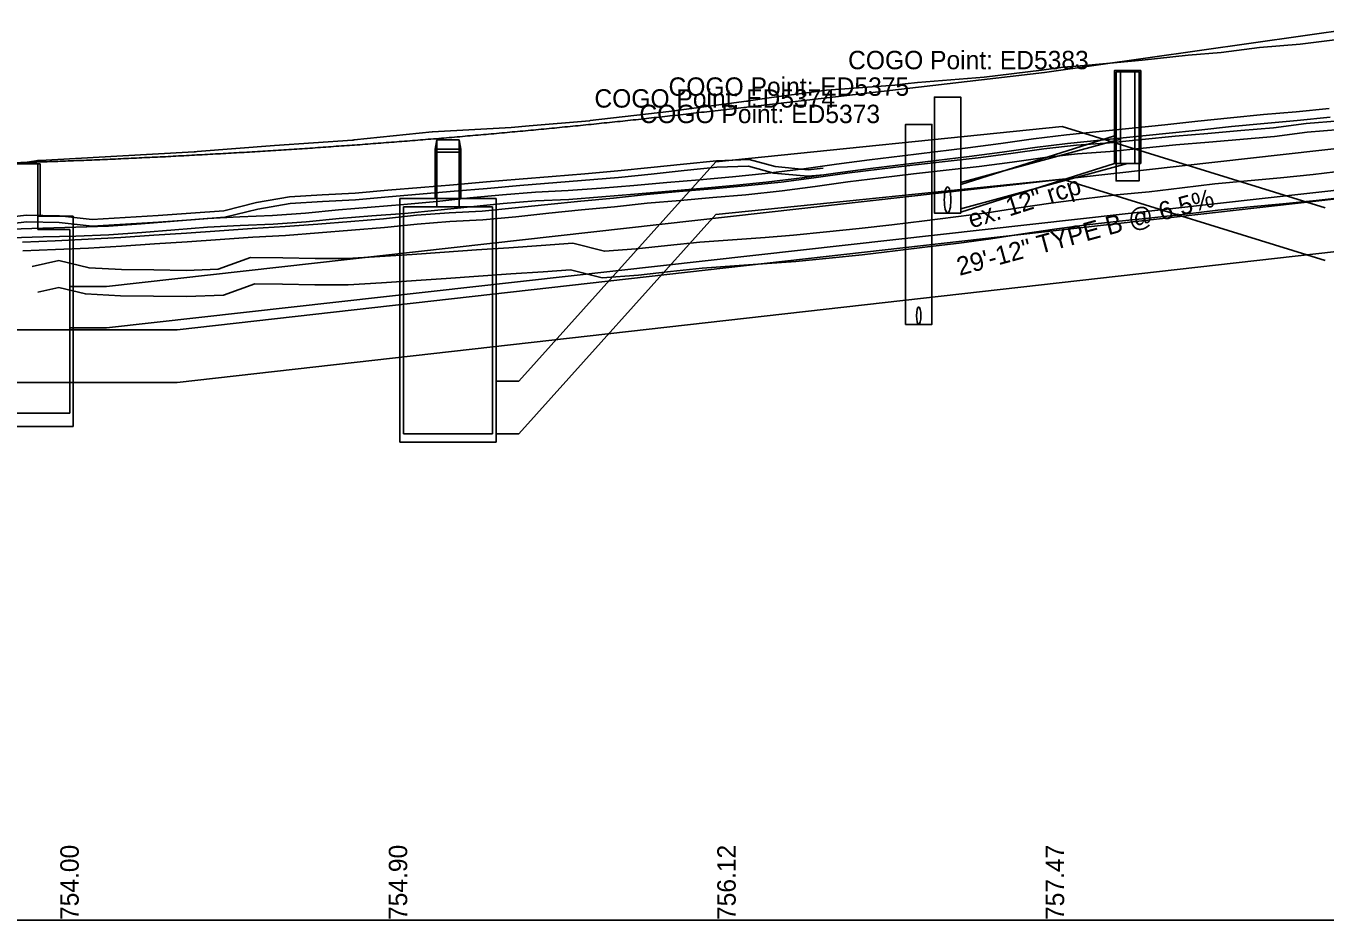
# Model space of a CAD drawing. Extents: x 1833473 to 1837132, y 704683 to 706683.
# Drawn here: x 1834152.8 to 1834350.5, y 705682.6 to 705818.8 of the extents above; entities that cross this region are included whole.
import ezdxf

# ---------------------------------------------------------------- set-up
doc = ezdxf.new("R2010")
doc.units = 0
for name, color, linetype in [('DR_P_Text', 7, 'Continuous'), ('DR_X_Storm_Sewer', 7, 'Continuous'), ('DR_X_Text', 7, 'Continuous'), ('GK_Cells', 7, 'Continuous'), ('PF_P_Grade_Line', 7, 'Continuous'), ('PF_X_Ground_Line', 7, 'Continuous'), ('PF_X_Text', 7, 'Continuous'), ('SC_Scratch1', 7, 'Continuous'), ('UT_P_Electric', 7, 'Continuous'), ('UT_P_Telecom', 7, 'Continuous'), ('UT_X_Electric', 7, 'Continuous'), ('UT_X_Gas', 7, 'Continuous'), ('UT_X_Sanitary_Line', 7, 'Continuous'), ('UT_X_Water', 7, 'Continuous')]:
    doc.layers.add(name, color=color, linetype=linetype)

msp = doc.modelspace()

# ---------------------------------------------------------------- linework, layer by layer
at = {"layer": 'DR_X_Storm_Sewer'}
for p, q in [((1834295.04, 705794.61), (1834318.44, 705802.05)), ((1834319.36, 705801.55), (1834295.04, 705794.93)), ((1834295.04, 705790.41), (1834318.44, 705797.85)), ((1834320.44, 705797.85), (1834295.04, 705790.93))]:
    msp.add_line(p, q, dxfattribs=at)
for points in [[(1834320.44, 705811.97), (1834318.44, 705811.97), (1834318.44, 705797.85), (1834322.44, 705797.85), (1834322.44, 705811.97), (1834320.44, 705811.97)], [(1834318.69, 705811.81), (1834318.69, 705795.18), (1834322.19, 705795.18), (1834322.19, 705811.81), (1834318.69, 705811.81)], [(1834319.36, 705811.81), (1834319.36, 705797.85), (1834321.52, 705797.85), (1834321.52, 705811.81)], [(1834293.04, 705807.93), (1834291.04, 705807.93), (1834291.04, 705790.29), (1834295.04, 705790.29), (1834295.04, 705807.93), (1834293.04, 705807.93)]]:
    msp.add_lwpolyline(points, dxfattribs=at)
msp.add_ellipse((1834293.04, 705792.29), major_axis=(0, 2), ratio=0.25, dxfattribs=at)
at = {"layer": 'GK_Cells'}
msp.add_line((1833710.78, 705682.65), (1834910.78, 705682.65), dxfattribs=at)
msp.add_line((1833710.78, 705682.65), (1834910.78, 705682.65), dxfattribs=at)
at = {"layer": 'PF_P_Grade_Line'}
for p, q in [((1834307.78, 705811.69), (1834357.78, 705818.77)), ((1834256.78, 705805.76), (1834307.78, 705811.69))]:
    msp.add_line(p, q, dxfattribs=at)
msp.add_spline([(1834096.78, 705797.41), (1834099.98, 705797.37), (1834103.18, 705797.35), (1834106.38, 705797.33), (1834109.58, 705797.32), (1834112.78, 705797.32), (1834115.98, 705797.33), (1834119.18, 705797.34), (1834122.38, 705797.36), (1834125.58, 705797.4), (1834128.78, 705797.44), (1834131.98, 705797.48), (1834135.18, 705797.54), (1834138.38, 705797.6), (1834141.58, 705797.68), (1834144.78, 705797.76), (1834147.98, 705797.85), (1834151.18, 705797.94), (1834154.38, 705798.05), (1834157.58, 705798.16), (1834160.78, 705798.28), (1834163.98, 705798.41), (1834167.18, 705798.55), (1834170.38, 705798.7), (1834173.58, 705798.85), (1834176.78, 705799.02), (1834179.98, 705799.19), (1834183.18, 705799.37), (1834186.38, 705799.55), (1834189.58, 705799.75), (1834192.78, 705799.95), (1834195.98, 705800.16), (1834199.18, 705800.39), (1834202.38, 705800.61), (1834205.58, 705800.85), (1834208.78, 705801.1), (1834211.98, 705801.35), (1834215.18, 705801.61), (1834218.38, 705801.88), (1834221.58, 705802.16), (1834224.78, 705802.44), (1834227.98, 705802.74), (1834231.18, 705803.04), (1834234.38, 705803.35), (1834237.58, 705803.67), (1834240.78, 705804), (1834243.98, 705804.33), (1834247.18, 705804.68), (1834250.38, 705805.03), (1834253.58, 705805.39), (1834256.78, 705805.76)], degree=3, dxfattribs=at)
at = {"layer": 'PF_X_Ground_Line'}
for points in [[(1834154.4, 705798.24), (1834154.57, 705798.27), (1834154.89, 705798.28), (1834166.57, 705798.97), (1834178.36, 705799.6), (1834178.57, 705799.62), (1834178.79, 705799.64), (1834190.57, 705800.55), (1834202.46, 705801.4), (1834202.57, 705801.4), (1834202.69, 705801.41), (1834214.57, 705802.65), (1834214.64, 705802.65), (1834226.58, 705803.3), (1834229.37, 705803.55), (1834238.54, 705804.35), (1834238.58, 705804.35), (1834238.61, 705804.36), (1834250.58, 705805.76), (1834262.44, 705807.33), (1834262.58, 705807.34), (1834262.72, 705807.36), (1834265.86, 705807.81), (1834274.59, 705809.02), (1834284.99, 705809.77), (1834286.6, 705809.97), (1834288.48, 705810.16), (1834298.62, 705810.96), (1834307.32, 705812.04), (1834310.64, 705812.51), (1834314.5, 705812.79), (1834322.65, 705813.54), (1834329.65, 705814.31), (1834334.67, 705814.74), (1834340.52, 705815.49), (1834346.68, 705816.02), (1834351.98, 705816.68)], [(1834148, 705797.28), (1834154.25, 705798.22), (1834154.4, 705798.24)]]:
    msp.add_lwpolyline(points, dxfattribs=at)
at = {"layer": 'UT_P_Electric'}
for p, q in [((1834165.01, 705779.12), (1834367.13, 705801.76)), ((1834149.99, 705797.8), (1834154.91, 705797.8)), ((1834154.57, 705787.8), (1834154.57, 705797.8)), ((1834154.91, 705789.8), (1834154.91, 705797.8)), ((1834165.01, 705772.79), (1834367.13, 705795.43)), ((1834154.57, 705789.8), (1834159.95, 705789.8)), ((1834159.95, 705789.8), (1834159.95, 705757.8)), ((1834154.57, 705787.8), (1834159.45, 705787.8)), ((1834159.45, 705787.8), (1834159.45, 705759.8)), ((1834165.01, 705779.12), (1834159.45, 705779.12)), ((1834165.01, 705772.79), (1834159.45, 705772.79)), ((1834159.45, 705759.8), (1834145.45, 705759.8)), ((1834159.95, 705757.8), (1834144.95, 705757.8))]:
    msp.add_line(p, q, dxfattribs=at)
at = {"layer": 'UT_P_Telecom'}
for p, q in [((1834175.78, 705772.5), (1834410.78, 705799.07)), ((1834175.78, 705764.5), (1834410.78, 705791.07)), ((1834142.47, 705772.5), (1834175.78, 705772.5)), ((1834142.47, 705764.5), (1834175.78, 705764.5))]:
    msp.add_line(p, q, dxfattribs=at)
at = {"layer": 'UT_X_Electric'}
for p, q in [((1834257.75, 705798.09), (1834310.49, 705803.46)), ((1834310.49, 705803.46), (1834350.49, 705791.07)), ((1834215.04, 705800.01), (1834215.3, 705801.41)), ((1834215.04, 705792.49), (1834215.04, 705800.01)), ((1834215.04, 705800.01), (1834218.93, 705800)), ((1834215.04, 705799.55), (1834218.91, 705799.55)), ((1834215.3, 705791.25), (1834215.3, 705801.41)), ((1834215.3, 705801.41), (1834218.68, 705801.41)), ((1834218.68, 705801.41), (1834218.68, 705791.25)), ((1834218.68, 705801.41), (1834218.93, 705800)), ((1834218.93, 705800), (1834218.93, 705792.49)), ((1834227.75, 705764.7), (1834257.75, 705798.09)), ((1834257.75, 705790.07), (1834310.49, 705795.45)), ((1834310.49, 705795.45), (1834350.49, 705783.06)), ((1834209.66, 705792.49), (1834224.31, 705792.49)), ((1834209.66, 705792.49), (1834209.66, 705755.4)), ((1834224.31, 705792.49), (1834224.31, 705755.4)), ((1834210.23, 705791.25), (1834223.75, 705791.25)), ((1834210.23, 705756.69), (1834210.23, 705791.25)), ((1834223.75, 705756.69), (1834223.75, 705791.25)), ((1834227.75, 705756.69), (1834257.75, 705790.07)), ((1834224.31, 705764.7), (1834227.75, 705764.7)), ((1834210.23, 705756.69), (1834223.75, 705756.69)), ((1834224.31, 705756.69), (1834227.75, 705756.69)), ((1834209.66, 705755.4), (1834224.31, 705755.4))]:
    msp.add_line(p, q, dxfattribs=at)
for points in [[(1834150.32, 705787.83), (1834155.32, 705787.98), (1834160.32, 705788.12), (1834165.32, 705788.29), (1834170.31, 705788.63), (1834175.31, 705789.06), (1834180.31, 705789.45), (1834185.3, 705789.71), (1834190.3, 705789.92), (1834195.3, 705790.29), (1834200.3, 705790.79), (1834205.29, 705791.19), (1834210.29, 705791.57), (1834215.29, 705792.05), (1834220.29, 705792.58), (1834225.29, 705793.08), (1834230.29, 705793.46), (1834235.29, 705793.7), (1834240.29, 705794.06), (1834245.29, 705794.5), (1834250.29, 705794.93), (1834255.29, 705795.36), (1834260.29, 705795.79), (1834265.29, 705796.33), (1834271.16, 705797.03), (1834276.15, 705797.73), (1834281.15, 705798.39), (1834286.15, 705799), (1834291.14, 705799.6), (1834296.14, 705800.23), (1834301.14, 705800.9), (1834306.13, 705801.61), (1834311.13, 705802.22), (1834316.13, 705802.68), (1834321.12, 705803.2), (1834326.12, 705803.73), (1834331.12, 705804.26), (1834336.11, 705804.79), (1834341.11, 705805.27), (1834346.1, 705805.71), (1834351.1, 705806.22)], [(1834150.38, 705786.49), (1834155.36, 705786.65), (1834160.36, 705786.79), (1834165.38, 705786.96), (1834170.41, 705787.3), (1834175.42, 705787.73), (1834180.39, 705788.12), (1834185.37, 705788.38), (1834190.38, 705788.59), (1834195.41, 705788.96), (1834200.41, 705789.46), (1834205.4, 705789.86), (1834210.41, 705790.24), (1834215.43, 705790.73), (1834220.43, 705791.25), (1834225.41, 705791.75), (1834230.37, 705792.13), (1834235.37, 705792.37), (1834240.4, 705792.73), (1834245.4, 705793.17), (1834255.4, 705794.03), (1834260.42, 705794.47), (1834265.44, 705795.01), (1834271.33, 705795.7), (1834276.33, 705796.41), (1834281.32, 705797.07), (1834291.3, 705798.28), (1834296.31, 705798.9), (1834301.32, 705799.58), (1834306.31, 705800.29), (1834311.27, 705800.89), (1834316.26, 705801.36), (1834321.26, 705801.87), (1834326.26, 705802.4), (1834331.26, 705802.93), (1834336.25, 705803.46), (1834341.23, 705803.94), (1834346.23, 705804.38), (1834351.25, 705804.89)], [(1834152.2, 705785.86), (1834157.2, 705786.08), (1834162.2, 705786.29), (1834167.2, 705786.55), (1834172.2, 705786.93), (1834177.2, 705787.24), (1834182.2, 705787.59), (1834187.19, 705787.95), (1834192.19, 705788.22), (1834197.19, 705788.6), (1834202.19, 705788.99), (1834207.19, 705789.43), (1834212.19, 705789.94), (1834217.19, 705790.32), (1834222.19, 705790.58), (1834227.19, 705791.06), (1834232.19, 705791.61), (1834237.19, 705792.11), (1834242.19, 705792.56), (1834247.19, 705793.11), (1834252.19, 705793.55), (1834257.19, 705793.98), (1834262.19, 705794.41), (1834267.7, 705795), (1834272.7, 705795.66), (1834277.69, 705796.35), (1834282.69, 705796.97), (1834287.69, 705797.58), (1834292.69, 705798.15), (1834297.69, 705798.67), (1834302.68, 705799.37), (1834307.68, 705800.07), (1834312.68, 705800.62), (1834317.68, 705800.98), (1834322.67, 705801.49), (1834327.67, 705801.98), (1834332.66, 705802.42), (1834337.66, 705802.84), (1834342.65, 705803.26), (1834347.64, 705803.91), (1834352.63, 705804.33)], [(1834152.28, 705784.52), (1834157.25, 705784.75), (1834162.26, 705784.96), (1834167.28, 705785.22), (1834172.29, 705785.6), (1834177.28, 705785.91), (1834182.29, 705786.26), (1834187.28, 705786.62), (1834192.28, 705786.89), (1834197.3, 705787.27), (1834202.3, 705787.66), (1834207.32, 705788.1), (1834212.31, 705788.61), (1834217.28, 705788.99), (1834222.29, 705789.25), (1834227.33, 705789.73), (1834232.33, 705790.29), (1834237.32, 705790.78), (1834242.33, 705791.23), (1834247.32, 705791.78), (1834252.31, 705792.22), (1834257.31, 705792.65), (1834262.32, 705793.08), (1834267.86, 705793.68), (1834272.87, 705794.33), (1834277.87, 705795.03), (1834282.86, 705795.65), (1834287.85, 705796.26), (1834292.83, 705796.82), (1834297.85, 705797.35), (1834302.87, 705798.05), (1834307.85, 705798.75), (1834312.8, 705799.29), (1834317.79, 705799.65), (1834322.81, 705800.16), (1834327.8, 705800.65), (1834332.78, 705801.09), (1834342.79, 705801.94), (1834347.78, 705802.59), (1834352.74, 705803.01)]]:
    msp.add_lwpolyline(points, dxfattribs=at)
at = {"layer": 'UT_X_Gas'}
for points in [[(1834147.85, 705789.39), (1834152.85, 705789.97), (1834157.85, 705789.84), (1834162.85, 705789.28), (1834167.85, 705789.59), (1834172.85, 705789.9), (1834177.85, 705790.26), (1834182.85, 705790.64), (1834187.85, 705791.88), (1834192.85, 705792.73), (1834197.85, 705793.04), (1834202.85, 705793.32), (1834207.84, 705793.75), (1834212.84, 705794.17), (1834217.84, 705794.6), (1834222.84, 705795.03), (1834227.84, 705795.47), (1834232.84, 705795.87), (1834237.84, 705796.28), (1834242.84, 705796.69), (1834247.84, 705797.22), (1834252.84, 705797.75), (1834257.84, 705798.26), (1834262.84, 705798.42), (1834266.79, 705797.36), (1834271.79, 705796.88), (1834274.1, 705797.1)], [(1834147.94, 705788.39), (1834152.89, 705788.96), (1834157.78, 705788.84), (1834162.82, 705788.27), (1834172.92, 705788.9), (1834177.92, 705789.27), (1834183.01, 705789.65), (1834188.05, 705790.9), (1834192.96, 705791.74), (1834197.9, 705792.04), (1834202.92, 705792.32), (1834207.93, 705792.75), (1834217.93, 705793.6), (1834222.93, 705794.04), (1834227.93, 705794.47), (1834242.93, 705795.69), (1834247.94, 705796.22), (1834252.94, 705796.76), (1834257.9, 705797.26), (1834262.72, 705797.42), (1834266.61, 705796.38), (1834271.78, 705795.88), (1834274.19, 705796.1)]]:
    msp.add_lwpolyline(points, dxfattribs=at)
at = {"layer": 'UT_X_Sanitary_Line'}
msp.add_lwpolyline([(1834288.64, 705803.77), (1834286.64, 705803.77), (1834286.64, 705773.33), (1834290.64, 705773.33), (1834290.64, 705803.77), (1834288.64, 705803.77)], dxfattribs=at)
msp.add_ellipse((1834288.64, 705774.66), major_axis=(0, 1.33), ratio=0.25, dxfattribs=at)
at = {"layer": 'UT_X_Water'}
for points in [[(1834153.71, 705782.14), (1834157.76, 705783.05), (1834162.37, 705781.94), (1834167.29, 705781.68), (1834172.2, 705781.62), (1834177.12, 705781.56), (1834182.03, 705781.76), (1834186.94, 705783.54), (1834191.86, 705783.46), (1834196.77, 705783.38), (1834201.69, 705783.36), (1834206.6, 705783.66), (1834211.52, 705784), (1834216.44, 705784.33), (1834221.35, 705784.67), (1834226.27, 705785.01), (1834231.19, 705785.35), (1834235.99, 705785.68), (1834240.8, 705784.48), (1834245.61, 705784.83), (1834250.41, 705785.37), (1834255.31, 705785.87), (1834260.31, 705786.23), (1834265.29, 705786.58), (1834269.6, 705786.9), (1834274.58, 705787.41), (1834279.57, 705787.93), (1834284.57, 705788.51), (1834289.5, 705789.12), (1834294.29, 705789.69), (1834299.08, 705790.31), (1834303.86, 705791.06), (1834308.76, 705791.8), (1834313.75, 705792.45), (1834318.73, 705793.04), (1834323.73, 705793.53), (1834328.72, 705794.11), (1834333.71, 705794.72), (1834338.71, 705795.2), (1834343.7, 705795.65), (1834348.7, 705796.17), (1834353.69, 705796.74)], [(1834154.58, 705778.24), (1834157.73, 705778.94), (1834161.8, 705777.97), (1834167.16, 705777.68), (1834177.17, 705777.56), (1834182.81, 705777.79), (1834187.61, 705779.53), (1834191.79, 705779.46), (1834196.73, 705779.38), (1834201.8, 705779.36), (1834206.86, 705779.67), (1834216.71, 705780.34), (1834221.63, 705780.68), (1834226.55, 705781.02), (1834231.46, 705781.36), (1834235.63, 705781.64), (1834240.45, 705780.44), (1834245.98, 705780.85), (1834250.84, 705781.39), (1834255.66, 705781.88), (1834260.6, 705782.24), (1834265.57, 705782.59), (1834269.96, 705782.91), (1834274.99, 705783.43), (1834280.01, 705783.95), (1834285.04, 705784.53), (1834289.99, 705785.14), (1834294.78, 705785.72), (1834299.64, 705786.35), (1834304.47, 705787.11), (1834309.32, 705787.84), (1834314.24, 705788.48), (1834319.16, 705789.06), (1834324.15, 705789.55), (1834329.19, 705790.14), (1834334.15, 705790.74), (1834339.08, 705791.22), (1834344.09, 705791.67), (1834349.13, 705792.2), (1834354.13, 705792.76)]]:
    msp.add_lwpolyline(points, dxfattribs=at)

# ---------------------------------------------------------------- texts
at = {"layer": 'DR_P_Text'}
msp.add_text('29\'-12" TYPE B @ 6.5%', height=2.8, rotation=15.2338, dxfattribs=at).set_placement((1834294.86, 705780.72))
at = {"layer": 'DR_X_Text'}
msp.add_text('ex. 12" rcp', height=2.8, rotation=17.6407, dxfattribs=at).set_placement((1834296.67, 705787.92))
at = {"layer": 'PF_X_Text'}
for s, p in [('754.00', (1834160.78, 705682.65)), ('754.90', (1834210.78, 705682.65)), ('756.12', (1834260.78, 705682.65)), ('757.47', (1834310.78, 705682.65))]:
    msp.add_text(s, height=2.8, rotation=90, dxfattribs=at).set_placement(p)
at = {"layer": 'SC_Scratch1'}
for s, p in [('COGO Point: ED5383', (1834277.89, 705812.18)), ('COGO Point: ED5375', (1834250.56, 705808.14)), ('COGO Point: ED5374', (1834239.28, 705806.34)), ('COGO Point: ED5373', (1834246.13, 705803.98))]:
    msp.add_text(s, height=2.8, dxfattribs=at).set_placement(p)

doc.saveas('drawing.dxf')
